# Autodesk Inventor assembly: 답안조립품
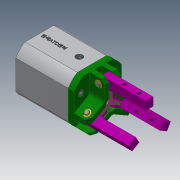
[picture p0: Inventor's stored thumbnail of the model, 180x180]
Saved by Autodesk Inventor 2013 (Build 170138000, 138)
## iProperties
Created: 2020-02
Part Number: 답안조립품
Document SubType Name: Assembly
Designer: user
Author: user
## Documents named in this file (13)
- C:\Users\user\Desktop\700206V1007\답안조립품.iam
- C:\Users\user\Desktop\700206V1007\본체.ipt
- C:\Users\user\Desktop\700206V1007\E링.ipt
- C:\Users\user\Desktop\700206V1007\O-RING 12x16.ipt
- C:\Users\user\Desktop\700206V1007\O-RING 18x22.ipt
- C:\Users\user\Desktop\700206V1007\O-RING 34x40.ipt
- C:\Users\user\Desktop\700206V1007\로드.ipt
- C:\Users\user\Desktop\700206V1007\본체헤드.ipt
- C:\Users\user\Desktop\700206V1007\볼트 M4.ipt
- C:\Users\user\Desktop\700206V1007\피스톤.ipt
- C:\Users\user\Desktop\700206V1007\핀 A.ipt
- C:\Users\user\Desktop\700206V1007\핀 B.ipt
- C:\Users\user\Desktop\700206V1007\핑거.ipt
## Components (20 placed, 8 different names)
1. E링:1
2. O-RING 12x16:1
3. O-RING 18x22:1
4. O-RING 34x40:1
5. 피스톤:1
6. 핀 A:1 — 플러쉬:1
7. 핀 B:1
8. 핑거:1 — 플러쉬:1
9. 핑거:2
10. 핑거:3 — 플러쉬:2
11. O-RING 34x40:2
12. 핀 A:2
13. 핀 A:3 — 플러쉬:2
14. 핀 B:2
15. 핀 B:3
16. E링:2
17. E링:3
18. E링:4
19. E링:5
20. E링:6
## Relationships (2: Flush 2)
- 플러쉬:1 [Flush]: 핀 A:1 ↔ 핑거:1
- 플러쉬:2 [Flush]: 핑거:3 ↔ 핀 A:3
